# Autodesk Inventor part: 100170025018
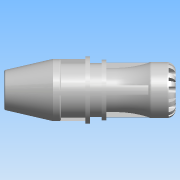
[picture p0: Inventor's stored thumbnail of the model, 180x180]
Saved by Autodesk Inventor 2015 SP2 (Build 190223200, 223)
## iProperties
Created: 2016-12
Part Number: 100170025018
Material: PVC-Piping
Description: PLASSON UNIVERSAL COUPLING 14-18X25 SERIES 1
Document SubType Name: Modeling
Designer: KIM
Density: 1.4 g/cm^3
Appearance: Smooth - White
Author: KIM
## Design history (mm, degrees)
derived "10017.ipt"
feature "Solid1::10017.ipt"
tag "TaggingFeature1"
body "Solid1"
other parameters: "d15" = 18, "d16" = 17.64, "d20" = 44.28, "d21" = 80 deg, "d22" = 19.57143, "d23" = 0, "d25" = 360 deg, "d48" = 1.25, "d52" = 0.54, "d72" = 25, "d73" = 48, "d74" = 2.5, "d79" = 31.25, "d80" = 20.16, "d81" = 77 deg, "d82" = 137, "d83" = 68.5, "d84" = 47, "d85" = 3.2, "d86" = 54, "d87" = 49.68, "d88" = 45, "d89" = 9.4, "d90" = 43.2, "d91" = 36, "d93" = 1.37, "d96" = 5.5, "d97" = 5.5, "d98" = 0, "d100" = 360 deg, "d103" = 0.5, "d104" = 0.5, "d105" = 8 deg, "d106" = 8 deg, "d108" = 0, "d110" = 360 deg, "d112" = 7.5, "d113" = 3.75, "d115" = 38.4, "d116" = 0, "d118" = 360 deg, "d120" = 5.4, "d121" = 0.54, "d_" = 25, "E_" = 54, "H_" = 137, "l_" = 48, "d_1" = 18, "l_1" = 47, "d66" = 76, "d68" = 41, "d69" = 45, "d70" = 20.955, "d71" = 13, "d92" = 6.875, "d94" = 45, "d102" = 31.25
